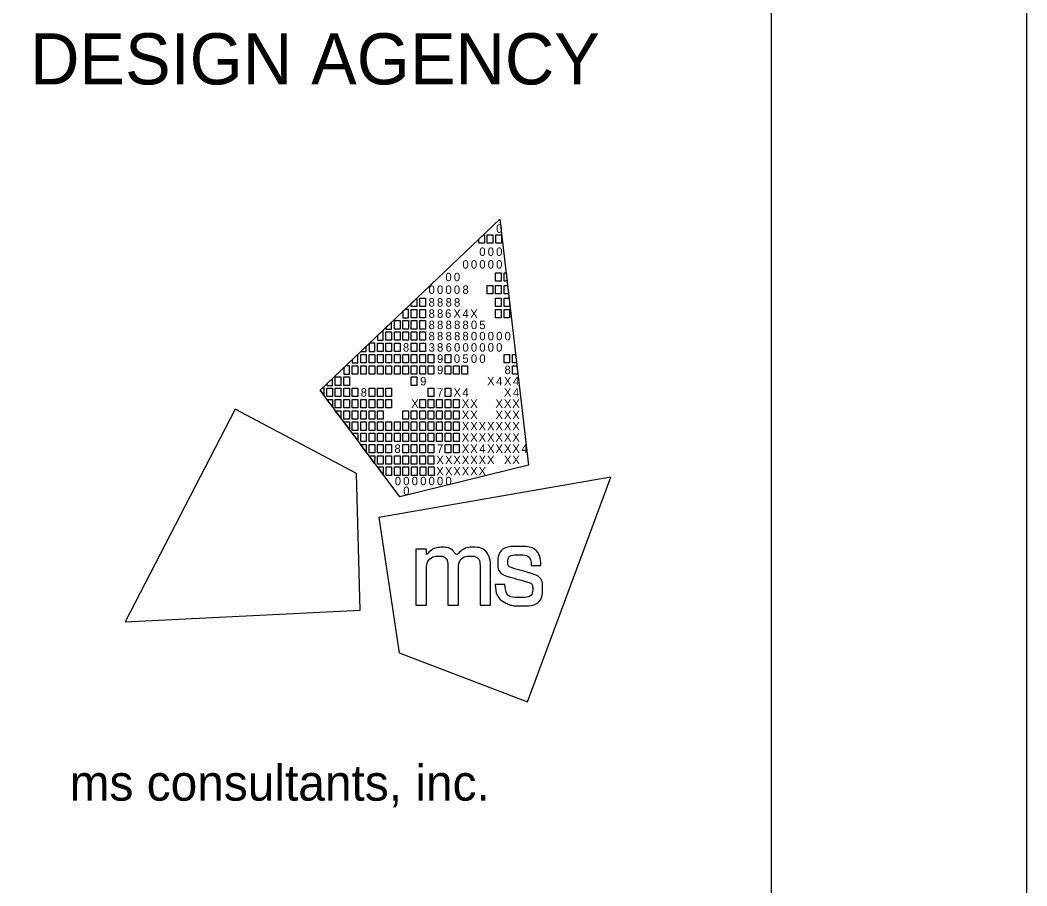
# Model space of a CAD drawing. Extents: x -1.2 to 34, y 0 to 22.
# Drawn here: x 32.03 to 34, y 2.782 to 4.476 of the extents above; entities that cross this region are included whole.
import ezdxf

# ---------------------------------------------------------------- set-up
doc = ezdxf.new("R2010")
doc.units = 0
for name, color, linetype in [('SH_Border', 7, 'Continuous'), ('SH_Cut_Line', 7, 'Continuous'), ('SH_Data', 7, 'Continuous')]:
    doc.layers.add(name, color=color, linetype=linetype)

msp = doc.modelspace()

# ---------------------------------------------------------------- linework, layer by layer
at = {"layer": 'SH_Border'}
for p, q in [((32.6175, 3.7519), (32.9688, 4.0861)), ((32.9688, 4.0861), (32.9688, 4.0861)), ((32.9688, 4.0861), (33.0253, 3.6052)), ((32.773, 3.543), (32.6175, 3.7519)), ((33.0253, 3.6052), (32.773, 3.543))]:
    msp.add_line(p, q, dxfattribs=at)
for points in [[(1.5, 21.5), (33.5, 21.5), (33.5, 0.5), (1.5, 0.5)], [(32.9279, 4.0472), (32.9369, 4.0558), (32.9389, 4.0558), (32.9389, 4.0393), (32.9279, 4.0393)], [(32.9444, 4.0558), (32.9554, 4.0558), (32.9554, 4.0393), (32.9444, 4.0393)], [(32.9609, 4.0558), (32.9719, 4.0558), (32.9719, 4.0393), (32.9609, 4.0393)], [(32.9606, 3.9815), (32.9716, 3.9815), (32.9716, 3.965), (32.9606, 3.965)], [(32.9771, 3.9815), (32.9811, 3.9815), (32.983, 3.965), (32.9771, 3.965)], [(32.9441, 3.9567), (32.9551, 3.9567), (32.9551, 3.9402), (32.9441, 3.9402)], [(32.9606, 3.9567), (32.9716, 3.9567), (32.9716, 3.9402), (32.9606, 3.9402)], [(32.9771, 3.9567), (32.984, 3.9567), (32.9859, 3.9402), (32.9771, 3.9402)], [(32.7953, 3.9211), (32.8064, 3.9316), (32.8064, 3.9154), (32.7953, 3.9154)], [(32.8123, 3.9319), (32.8233, 3.9319), (32.8233, 3.9154), (32.8123, 3.9154)], [(32.9606, 3.9319), (32.9716, 3.9319), (32.9716, 3.9154), (32.9606, 3.9154)], [(32.9771, 3.9319), (32.9869, 3.9319), (32.9881, 3.9218), (32.9881, 3.9154), (32.9771, 3.9154)], [(32.7958, 3.9099), (32.8068, 3.9099), (32.8068, 3.8934), (32.7958, 3.8934)], [(32.8123, 3.9099), (32.8233, 3.9099), (32.8233, 3.8934), (32.8123, 3.8934)], [(32.9606, 3.9099), (32.9716, 3.9099), (32.9716, 3.8934), (32.9606, 3.8934)], [(32.9771, 3.9099), (32.9881, 3.9099), (32.9881, 3.8934), (32.9771, 3.8934)], [(32.7627, 3.8879), (32.7737, 3.8879), (32.7737, 3.8714), (32.7627, 3.8714)], [(32.7793, 3.8879), (32.7903, 3.8879), (32.7903, 3.8714), (32.7793, 3.8714)], [(32.7958, 3.8879), (32.8068, 3.8879), (32.8068, 3.8714), (32.7958, 3.8714)], [(32.8123, 3.8879), (32.8233, 3.8879), (32.8233, 3.8714), (32.8123, 3.8714)], [(32.7462, 3.8659), (32.7572, 3.8659), (32.7572, 3.8494), (32.7462, 3.8494)], [(32.7627, 3.8659), (32.7737, 3.8659), (32.7737, 3.8494), (32.7627, 3.8494)], [(32.7793, 3.8659), (32.7903, 3.8659), (32.7903, 3.8494), (32.7793, 3.8494)], [(32.7958, 3.8659), (32.8068, 3.8659), (32.8068, 3.8494), (32.7958, 3.8494)], [(32.8123, 3.8659), (32.8233, 3.8659), (32.8233, 3.8494), (32.8123, 3.8494)], [(32.7297, 3.8439), (32.7407, 3.8439), (32.7407, 3.8273), (32.7297, 3.8273)], [(32.7462, 3.8439), (32.7572, 3.8439), (32.7572, 3.8273), (32.7462, 3.8273)], [(32.7627, 3.8439), (32.7737, 3.8439), (32.7737, 3.8273), (32.7627, 3.8273)], [(32.7958, 3.8439), (32.8068, 3.8439), (32.8068, 3.8273), (32.7958, 3.8273)], [(32.8123, 3.8439), (32.8233, 3.8439), (32.8233, 3.8273), (32.8123, 3.8273)], [(32.6967, 3.8218), (32.7077, 3.8218), (32.7077, 3.8053), (32.6967, 3.8053)], [(32.7132, 3.8218), (32.7242, 3.8218), (32.7242, 3.8053), (32.7132, 3.8053)], [(32.7297, 3.8218), (32.7407, 3.8218), (32.7407, 3.8053), (32.7297, 3.8053)], [(32.7462, 3.8218), (32.7572, 3.8218), (32.7572, 3.8053), (32.7462, 3.8053)], [(32.7627, 3.8218), (32.7737, 3.8218), (32.7737, 3.8053), (32.7627, 3.8053)], [(32.7793, 3.8218), (32.7903, 3.8218), (32.7903, 3.8053), (32.7793, 3.8053)], [(32.7958, 3.8218), (32.8068, 3.8218), (32.8068, 3.8053), (32.7958, 3.8053)], [(32.8123, 3.8218), (32.8233, 3.8218), (32.8233, 3.8053), (32.8123, 3.8053)], [(32.8288, 3.8218), (32.8398, 3.8218), (32.8398, 3.8053), (32.8288, 3.8053)], [(32.8618, 3.8218), (32.8728, 3.8218), (32.8728, 3.8053), (32.8618, 3.8053)], [(32.9771, 3.8218), (32.9881, 3.8218), (32.9881, 3.8053), (32.9771, 3.8053)], [(32.9935, 3.8218), (32.9998, 3.8218), (33.0018, 3.8053), (32.9935, 3.8053)], [(32.6802, 3.7998), (32.6912, 3.7998), (32.6912, 3.7833), (32.6802, 3.7833)], [(32.6967, 3.7998), (32.7077, 3.7998), (32.7077, 3.7833), (32.6967, 3.7833)], [(32.7132, 3.7998), (32.7242, 3.7998), (32.7242, 3.7833), (32.7132, 3.7833)], [(32.7297, 3.7998), (32.7407, 3.7998), (32.7407, 3.7833), (32.7297, 3.7833)], [(32.7462, 3.7998), (32.7572, 3.7998), (32.7572, 3.7833), (32.7462, 3.7833)], [(32.7627, 3.7998), (32.7737, 3.7998), (32.7737, 3.7833), (32.7627, 3.7833)], [(32.7793, 3.7998), (32.7903, 3.7998), (32.7903, 3.7833), (32.7793, 3.7833)], [(32.7958, 3.7998), (32.8068, 3.7998), (32.8068, 3.7833), (32.7958, 3.7833)], [(32.8123, 3.7998), (32.8233, 3.7998), (32.8233, 3.7833), (32.8123, 3.7833)], [(32.8288, 3.7998), (32.8398, 3.7998), (32.8398, 3.7833), (32.8288, 3.7833)], [(32.8618, 3.7998), (32.8728, 3.7998), (32.8728, 3.7833), (32.8618, 3.7833)], [(32.8783, 3.7998), (32.8893, 3.7998), (32.8893, 3.7833), (32.8783, 3.7833)], [(32.8947, 3.7998), (32.9057, 3.7998), (32.9057, 3.7833), (32.8947, 3.7833)], [(32.9935, 3.7998), (33.0024, 3.7998), (33.0044, 3.7833), (32.9935, 3.7833)], [(32.6471, 3.7778), (32.6581, 3.7778), (32.6581, 3.7613), (32.6471, 3.7613)], [(32.6637, 3.7778), (32.6747, 3.7778), (32.6747, 3.7613), (32.6637, 3.7613)], [(32.7958, 3.7778), (32.8068, 3.7778), (32.8068, 3.7613), (32.7958, 3.7613)], [(32.6306, 3.7558), (32.6416, 3.7558), (32.6416, 3.7393), (32.6306, 3.7393)], [(32.6471, 3.7558), (32.6581, 3.7558), (32.6581, 3.7393), (32.6471, 3.7393)], [(32.6637, 3.7558), (32.6747, 3.7558), (32.6747, 3.7393), (32.6637, 3.7393)], [(32.6802, 3.7558), (32.6912, 3.7558), (32.6912, 3.7393), (32.6802, 3.7393)], [(32.7132, 3.7558), (32.7242, 3.7558), (32.7242, 3.7393), (32.7132, 3.7393)], [(32.7297, 3.7558), (32.7407, 3.7558), (32.7407, 3.7393), (32.7297, 3.7393)], [(32.7462, 3.7558), (32.7572, 3.7558), (32.7572, 3.7393), (32.7462, 3.7393)], [(32.8288, 3.7558), (32.8398, 3.7558), (32.8398, 3.7393), (32.8288, 3.7393)], [(32.8618, 3.7558), (32.8728, 3.7558), (32.8728, 3.7393), (32.8618, 3.7393)], [(32.6306, 3.7338), (32.6416, 3.7338), (32.6416, 3.72)], [(32.6471, 3.7338), (32.6581, 3.7338), (32.6581, 3.7173), (32.6471, 3.7173)], [(32.6637, 3.7338), (32.6747, 3.7338), (32.6747, 3.7173), (32.6637, 3.7173)], [(32.6802, 3.7338), (32.6912, 3.7338), (32.6912, 3.7173), (32.6802, 3.7173)], [(32.6967, 3.7338), (32.7077, 3.7338), (32.7077, 3.7173), (32.6967, 3.7173)], [(32.7132, 3.7338), (32.7242, 3.7338), (32.7242, 3.7173), (32.7132, 3.7173)], [(32.7297, 3.7338), (32.7407, 3.7338), (32.7407, 3.7173), (32.7297, 3.7173)], [(32.7462, 3.7338), (32.7572, 3.7338), (32.7572, 3.7173), (32.7462, 3.7173)], [(32.8123, 3.7338), (32.8233, 3.7338), (32.8233, 3.7173), (32.8123, 3.7173)], [(32.8288, 3.7338), (32.8398, 3.7338), (32.8398, 3.7173), (32.8288, 3.7173)], [(32.8453, 3.7338), (32.8563, 3.7338), (32.8563, 3.7173), (32.8453, 3.7173)], [(32.8618, 3.7338), (32.8728, 3.7338), (32.8728, 3.7173), (32.8618, 3.7173)], [(32.8783, 3.7338), (32.8893, 3.7338), (32.8893, 3.7173), (32.8783, 3.7173)], [(32.6471, 3.7117), (32.6581, 3.7117), (32.6581, 3.698)], [(32.6637, 3.7117), (32.6747, 3.7117), (32.6747, 3.6952), (32.6637, 3.6952)], [(32.6802, 3.7117), (32.6912, 3.7117), (32.6912, 3.6952), (32.6802, 3.6952)], [(32.6967, 3.7117), (32.7077, 3.7117), (32.7077, 3.6952), (32.6967, 3.6952)], [(32.7132, 3.7117), (32.7242, 3.7117), (32.7242, 3.6952), (32.7132, 3.6952)], [(32.7297, 3.7117), (32.7407, 3.7117), (32.7407, 3.6952), (32.7297, 3.6952)], [(32.7793, 3.7117), (32.7903, 3.7117), (32.7903, 3.6952), (32.7793, 3.6952)], [(32.7958, 3.7117), (32.8068, 3.7117), (32.8068, 3.6952), (32.7958, 3.6952)], [(32.8123, 3.7117), (32.8233, 3.7117), (32.8233, 3.6952), (32.8123, 3.6952)], [(32.8288, 3.7117), (32.8398, 3.7117), (32.8398, 3.6952), (32.8288, 3.6952)], [(32.8453, 3.7117), (32.8563, 3.7117), (32.8563, 3.6952), (32.8453, 3.6952)], [(32.8618, 3.7117), (32.8728, 3.7117), (32.8728, 3.6952), (32.8618, 3.6952)], [(32.8783, 3.7117), (32.8893, 3.7117), (32.8893, 3.6952), (32.8783, 3.6952)], [(32.6637, 3.6897), (32.6747, 3.6897), (32.6747, 3.676)], [(32.6747, 3.6897), (32.6747, 3.6897), (32.6747, 3.6897)], [(32.6802, 3.6897), (32.6912, 3.6897), (32.6912, 3.6732), (32.6802, 3.6732)], [(32.6967, 3.6897), (32.7077, 3.6897), (32.7077, 3.6732), (32.6967, 3.6732)], [(32.7132, 3.6897), (32.7242, 3.6897), (32.7242, 3.6732), (32.7132, 3.6732)], [(32.7297, 3.6897), (32.7407, 3.6897), (32.7407, 3.6732), (32.7297, 3.6732)], [(32.7462, 3.6897), (32.7572, 3.6897), (32.7572, 3.6732), (32.7462, 3.6732)], [(32.7627, 3.6897), (32.7737, 3.6897), (32.7737, 3.6732), (32.7627, 3.6732)], [(32.7793, 3.6897), (32.7903, 3.6897), (32.7903, 3.6732), (32.7793, 3.6732)], [(32.7958, 3.6897), (32.8068, 3.6897), (32.8068, 3.6732), (32.7958, 3.6732)], [(32.8123, 3.6897), (32.8233, 3.6897), (32.8233, 3.6732), (32.8123, 3.6732)], [(32.8288, 3.6897), (32.8398, 3.6897), (32.8398, 3.6732), (32.8288, 3.6732)], [(32.8453, 3.6897), (32.8563, 3.6897), (32.8563, 3.6732), (32.8453, 3.6732)], [(32.8618, 3.6897), (32.8728, 3.6897), (32.8728, 3.6732), (32.8618, 3.6732)], [(32.8783, 3.6897), (32.8893, 3.6897), (32.8893, 3.6732), (32.8783, 3.6732)], [(32.6802, 3.6677), (32.6912, 3.6677), (32.6912, 3.654)], [(32.6967, 3.6677), (32.7077, 3.6677), (32.7077, 3.6512), (32.6967, 3.6512)], [(32.7132, 3.6677), (32.7242, 3.6677), (32.7242, 3.6512), (32.7132, 3.6512)], [(32.7297, 3.6677), (32.7407, 3.6677), (32.7407, 3.6512), (32.7297, 3.6512)], [(32.7462, 3.6677), (32.7572, 3.6677), (32.7572, 3.6512), (32.7462, 3.6512)], [(32.7627, 3.6677), (32.7737, 3.6677), (32.7737, 3.6512), (32.7627, 3.6512)], [(32.7793, 3.6677), (32.7903, 3.6677), (32.7903, 3.6512), (32.7793, 3.6512)], [(32.7958, 3.6677), (32.8068, 3.6677), (32.8068, 3.6512), (32.7958, 3.6512)], [(32.8123, 3.6677), (32.8233, 3.6677), (32.8233, 3.6512), (32.8123, 3.6512)], [(32.8288, 3.6677), (32.8398, 3.6677), (32.8398, 3.6512), (32.8288, 3.6512)], [(32.8453, 3.6677), (32.8563, 3.6677), (32.8563, 3.6512), (32.8453, 3.6512)], [(32.8618, 3.6677), (32.8728, 3.6677), (32.8728, 3.6512), (32.8618, 3.6512)], [(32.8783, 3.6677), (32.8893, 3.6677), (32.8893, 3.6512), (32.8783, 3.6512)], [(32.7077, 3.6305), (32.6965, 3.6457), (32.7077, 3.6457)], [(32.7132, 3.6457), (32.7242, 3.6457), (32.7242, 3.6292), (32.7132, 3.6292)], [(32.7297, 3.6457), (32.7407, 3.6457), (32.7407, 3.6292), (32.7297, 3.6292)], [(32.7462, 3.6457), (32.7572, 3.6457), (32.7572, 3.6292), (32.7462, 3.6292)], [(32.7793, 3.6457), (32.7903, 3.6457), (32.7903, 3.6292), (32.7793, 3.6292)], [(32.7958, 3.6457), (32.8068, 3.6457), (32.8068, 3.6292), (32.7958, 3.6292)], [(32.8123, 3.6457), (32.8233, 3.6457), (32.8233, 3.6292), (32.8123, 3.6292)], [(32.8288, 3.6457), (32.8398, 3.6457), (32.8398, 3.6292), (32.8288, 3.6292)], [(32.8618, 3.6457), (32.8728, 3.6457), (32.8728, 3.6292), (32.8618, 3.6292)], [(32.8783, 3.6457), (32.8893, 3.6457), (32.8893, 3.6292), (32.8783, 3.6292)], [(32.724, 3.6082), (32.7132, 3.6237), (32.7242, 3.6237)], [(32.7297, 3.6237), (32.7407, 3.6237), (32.7407, 3.6072), (32.7297, 3.6072)], [(32.7462, 3.6237), (32.7572, 3.6237), (32.7572, 3.6072), (32.7462, 3.6072)], [(32.7627, 3.6237), (32.7737, 3.6237), (32.7737, 3.6072), (32.7627, 3.6072)], [(32.7793, 3.6237), (32.7903, 3.6237), (32.7903, 3.6072), (32.7793, 3.6072)], [(32.7958, 3.6237), (32.8068, 3.6237), (32.8068, 3.6072), (32.7958, 3.6072)], [(32.8123, 3.6237), (32.8233, 3.6237), (32.8233, 3.6072), (32.8123, 3.6072)], [(32.8288, 3.6237), (32.8398, 3.6237), (32.8398, 3.6072), (32.8288, 3.6072)], [(32.7302, 3.6017), (32.7407, 3.6017), (32.7408, 3.5875)], [(32.7463, 3.6017), (32.7573, 3.6017), (32.7573, 3.5852), (32.7463, 3.5852)], [(32.763, 3.6017), (32.774, 3.6017), (32.774, 3.5852), (32.763, 3.5852)], [(32.7794, 3.6017), (32.7904, 3.6017), (32.7904, 3.5852), (32.7794, 3.5852)], [(32.796, 3.6017), (32.807, 3.6017), (32.807, 3.5852), (32.796, 3.5852)], [(32.8129, 3.6017), (32.8239, 3.6017), (32.8239, 3.5851), (32.8129, 3.5851)], [(32.8296, 3.6017), (32.8406, 3.6017), (32.8406, 3.5851), (32.8296, 3.5851)]]:
    msp.add_lwpolyline(points, close=True, dxfattribs=at)
for points in [[(32.7903, 3.9099), (32.7836, 3.9099), (32.7793, 3.9058), (32.7793, 3.8934), (32.7903, 3.8934), (32.7903, 3.9099)], [(32.7572, 3.8849), (32.7462, 3.8744), (32.7462, 3.8714), (32.7572, 3.8714), (32.7572, 3.8849)], [(32.7407, 3.8691), (32.7297, 3.8587), (32.7297, 3.8494), (32.7407, 3.8494), (32.7407, 3.8691)], [(32.7242, 3.8439), (32.7141, 3.8439), (32.7132, 3.843), (32.7132, 3.8273), (32.7242, 3.8273), (32.7242, 3.8439)], [(32.6912, 3.822), (32.6802, 3.8115), (32.6802, 3.8053), (32.6912, 3.8053), (32.6912, 3.822)], [(32.7077, 3.8377), (32.6968, 3.8273), (32.7077, 3.8273), (32.7077, 3.8377)], [(32.6747, 3.7998), (32.6679, 3.7998), (32.6637, 3.7958), (32.6637, 3.7833), (32.6747, 3.7833), (32.6747, 3.7998)], [(32.6416, 3.7749), (32.6306, 3.7644), (32.6306, 3.7613), (32.6416, 3.7613), (32.6416, 3.7749)], [(32.6251, 3.7558), (32.6216, 3.7558), (32.6175, 3.7519), (32.6251, 3.7417), (32.6251, 3.7558)], [(32.4512, 3.7149), (32.2359, 3.2988), (32.6956, 3.3215), (32.6884, 3.5892), (32.4512, 3.7149)], [(33.0229, 3.1422), (33.1859, 3.5814), (32.7324, 3.5029), (32.7722, 3.2381), (33.0229, 3.1422)]]:
    msp.add_lwpolyline(points, dxfattribs=at)
for points in [[(32.8048, 3.3315), (32.8048, 3.3315), (32.8048, 3.4409), (32.8048, 3.4409), (32.8048, 3.4409), (32.8255, 3.4409), (32.8255, 3.4409), (32.8255, 3.4409), (32.8255, 3.4297), (32.8255, 3.4297), (32.8346, 3.4399), (32.8457, 3.4445), (32.8555, 3.4445), (32.8688, 3.4445), (32.8791, 3.4372), (32.8837, 3.4266), (32.8915, 3.4381), (32.905, 3.4446), (32.9166, 3.4446), (32.9325, 3.4446), (32.9451, 3.435), (32.9494, 3.4213), (32.9494, 3.4212), (32.9494, 3.4212), (32.9494, 3.4212), (32.9501, 3.419), (32.9506, 3.4172), (32.9506, 3.4071), (32.9506, 3.4071), (32.9506, 3.3314), (32.9506, 3.3314), (32.9506, 3.3314), (32.9303, 3.3314), (32.9303, 3.3314), (32.9303, 3.3314), (32.9303, 3.4048), (32.9303, 3.4048), (32.9303, 3.4201), (32.9219, 3.4274), (32.911, 3.4274), (32.8995, 3.4274), (32.8879, 3.4171), (32.8879, 3.4001), (32.8879, 3.4001), (32.8879, 3.3315), (32.8879, 3.3315), (32.8879, 3.3315), (32.8674, 3.3315), (32.8674, 3.3315), (32.8674, 3.3315), (32.8674, 3.4059), (32.8674, 3.4059), (32.8674, 3.4203), (32.8588, 3.4274), (32.8496, 3.4274), (32.8384, 3.4274), (32.8254, 3.417), (32.8254, 3.3962), (32.8254, 3.3962), (32.8254, 3.3315), (32.8254, 3.3315), (32.8254, 3.3315), (32.8048, 3.3315), (32.8048, 3.3315)], [(32.9595, 3.3709), (32.9595, 3.3709), (32.9595, 3.3717), (32.9595, 3.3717), (32.9595, 3.3717), (32.9603, 3.3717), (32.9603, 3.3717), (32.9603, 3.3717), (32.9783, 3.3717), (32.9783, 3.3717), (32.9783, 3.3717), (32.9789, 3.3717), (32.9789, 3.3717), (32.9789, 3.3717), (32.979, 3.371), (32.979, 3.371), (32.9803, 3.3554), (32.9887, 3.346), (33.009, 3.346), (33.0273, 3.346), (33.0333, 3.3554), (33.0333, 3.3631), (33.0333, 3.3732), (33.0256, 3.3758), (33.0175, 3.378), (33.0175, 3.378), (32.987, 3.3867), (32.987, 3.3867), (32.972, 3.3909), (32.9648, 3.4019), (32.9648, 3.4142), (32.9648, 3.4303), (32.9768, 3.4462), (33.0052, 3.4462), (33.0348, 3.4462), (33.0489, 3.4285), (33.0489, 3.4095), (33.0489, 3.4095), (33.0489, 3.4087), (33.0489, 3.4087), (33.0489, 3.4087), (33.0482, 3.4087), (33.0482, 3.4087), (33.0482, 3.4087), (33.0312, 3.4087), (33.0312, 3.4087), (33.0312, 3.4087), (33.0305, 3.4087), (33.0305, 3.4087), (33.0305, 3.4087), (33.0305, 3.4094), (33.0305, 3.4094), (33.0301, 3.4208), (33.0226, 3.43), (33.0056, 3.43), (32.9891, 3.43), (32.9843, 3.4218), (32.9843, 3.4157), (32.9843, 3.4108), (32.9869, 3.4059), (32.9959, 3.4033), (32.9959, 3.4033), (33.0255, 3.3948), (33.0255, 3.3948), (33.0462, 3.3889), (33.0527, 3.3777), (33.0527, 3.3639), (33.0527, 3.3462), (33.041, 3.3298), (33.0087, 3.3298), (32.9952, 3.3298), (32.9877, 3.3321), (32.9823, 3.3348), (32.969, 3.3414), (32.9609, 3.3536), (32.9595, 3.3709)]]:
    msp.add_open_spline(points, degree=3, dxfattribs=at)
at = {"layer": 'SH_Cut_Line'}
msp.add_lwpolyline([(0, 0), (34, 0), (34, 22), (0, 22)], close=True, dxfattribs=at)
at = {"layer": 'SH_Data'}
msp.add_line((32.75, 3.5), (32.75, 3.5), dxfattribs=at)

# ---------------------------------------------------------------- texts
at = {"layer": 'SH_Border'}
for s, height, p in [('0', 0.0165, (32.9617, 4.0597)), ('0', 0.0165, (32.9288, 4.0145)), ('0', 0.0165, (32.9452, 4.0145)), ('0', 0.0165, (32.9617, 4.0145)), ('0', 0.0165, (32.8958, 3.9897)), ('0', 0.0165, (32.9123, 3.9897)), ('0', 0.0165, (32.9288, 3.9897)), ('0', 0.0165, (32.9452, 3.9897)), ('0', 0.0165, (32.9617, 3.9897)), ('0', 0.0165, (32.8625, 3.965)), ('0', 0.0165, (32.879, 3.965)), ('0', 0.0165, (32.8295, 3.9402)), ('0', 0.0165, (32.846, 3.9402)), ('0', 0.0165, (32.8625, 3.9402)), ('0', 0.0165, (32.879, 3.9402)), ('8', 0.0165, (32.8958, 3.9402)), ('8', 0.0165, (32.8295, 3.9154)), ('8', 0.0165, (32.846, 3.9154)), ('8', 0.0165, (32.8628, 3.9154)), ('8', 0.0165, (32.8793, 3.9154)), ('8', 0.0165, (32.8295, 3.8934)), ('8', 0.0165, (32.846, 3.8934)), ('6', 0.0165, (32.8618, 3.8934)), ('X', 0.0165, (32.8781, 3.8934)), ('4', 0.0165, (32.8958, 3.8934)), ('X', 0.0165, (32.911, 3.8934)), ('8', 0.0165, (32.8295, 3.8713)), ('8', 0.0165, (32.846, 3.8713)), ('8', 0.0165, (32.8628, 3.8713)), ('8', 0.0165, (32.8794, 3.8713)), ('8', 0.0165, (32.8958, 3.8713)), ('0', 0.0165, (32.9123, 3.8713)), ('5', 0.0165, (32.9287, 3.8713)), ('8', 0.0165, (32.8295, 3.8494)), ('8', 0.0165, (32.846, 3.8494)), ('8', 0.0165, (32.8628, 3.8494)), ('8', 0.0165, (32.8794, 3.8494)), ('8', 0.0165, (32.8958, 3.8494)), ('0', 0.0165, (32.9123, 3.8494)), ('0', 0.0165, (32.9288, 3.8494)), ('0', 0.0165, (32.9452, 3.8494)), ('0', 0.0165, (32.9617, 3.8494)), ('0', 0.0165, (32.9782, 3.8494)), ('8', 0.0165, (32.7793, 3.8273)), ('3', 0.0165, (32.8295, 3.8273)), ('8', 0.0165, (32.846, 3.8273)), ('6', 0.0165, (32.8629, 3.8273)), ('0', 0.0165, (32.8793, 3.8273)), ('0', 0.0165, (32.8958, 3.8273)), ('0', 0.0165, (32.9123, 3.8273)), ('0', 0.0165, (32.9288, 3.8273)), ('0', 0.0165, (32.9452, 3.8273)), ('0', 0.0165, (32.9617, 3.8273)), ('9', 0.0165, (32.846, 3.8053)), ('0', 0.0165, (32.879, 3.8053)), ('5', 0.0165, (32.8957, 3.8053)), ('0', 0.0165, (32.9123, 3.8053)), ('0', 0.0165, (32.9288, 3.8053)), ('9', 0.0165, (32.846, 3.7833)), ('8', 0.0165, (32.9781, 3.7833)), ('9', 0.0165, (32.813, 3.7613)), ('X', 0.0165, (32.9439, 3.7613)), ('4', 0.0165, (32.9617, 3.7613)), ('X', 0.0165, (32.9769, 3.7613)), ('4', 0.0165, (32.9946, 3.7613)), ('8', 0.0165, (32.6967, 3.7393)), ('7', 0.0165, (32.846, 3.7393)), ('X', 0.0165, (32.8781, 3.7393)), ('4', 0.0165, (32.8958, 3.7393)), ('X', 0.0165, (32.9769, 3.7393)), ('4', 0.0165, (32.9946, 3.7393)), ('X', 0.0165, (32.7955, 3.7173)), ('X', 0.0165, (32.8945, 3.7173)), ('X', 0.0165, (32.911, 3.7173)), ('X', 0.0165, (32.9604, 3.7173)), ('X', 0.0165, (32.9769, 3.7173)), ('X', 0.0165, (32.9933, 3.7173)), ('X', 0.0165, (32.8945, 3.6952)), ('X', 0.0165, (32.911, 3.6952)), ('X', 0.0165, (32.9604, 3.6952)), ('X', 0.0165, (32.9769, 3.6952)), ('X', 0.0165, (32.9933, 3.6952)), ('X', 0.0165, (32.8945, 3.6732)), ('X', 0.0165, (32.911, 3.6732)), ('X', 0.0165, (32.9274, 3.6732)), ('X', 0.0165, (32.9439, 3.6732)), ('X', 0.0165, (32.9604, 3.6732)), ('X', 0.0165, (32.9769, 3.6732)), ('X', 0.0165, (32.9933, 3.6732)), ('X', 0.0165, (32.8945, 3.6512)), ('X', 0.0165, (32.911, 3.6512)), ('X', 0.0165, (32.9274, 3.6512)), ('X', 0.0165, (32.9439, 3.6512)), ('X', 0.0165, (32.9604, 3.6512)), ('X', 0.0165, (32.9769, 3.6512)), ('X', 0.0165, (32.9933, 3.6512)), ('8', 0.0165, (32.7627, 3.6292)), ('7', 0.0165, (32.846, 3.6292)), ('X', 0.0165, (32.8945, 3.6292)), ('X', 0.0165, (32.911, 3.6292)), ('4', 0.0165, (32.9288, 3.6292)), ('X', 0.0165, (32.9439, 3.6292)), ('X', 0.0165, (32.9604, 3.6292)), ('X', 0.0165, (32.9769, 3.6292)), ('X', 0.0165, (32.9933, 3.6292)), ('4', 0.0165, (33.0111, 3.6292)), ('X', 0.0165, (32.8447, 3.6072)), ('X', 0.0165, (32.8616, 3.6072)), ('X', 0.0165, (32.878, 3.6072)), ('X', 0.0165, (32.8945, 3.6072)), ('X', 0.0165, (32.911, 3.6072)), ('X', 0.0165, (32.9274, 3.6072)), ('X', 0.0165, (32.9439, 3.6072)), ('X', 0.0165, (32.9771, 3.6072)), ('X', 0.0165, (32.9933, 3.6072)), ('X', 0.0165, (32.8447, 3.5851)), ('X', 0.0165, (32.8616, 3.5851)), ('X', 0.0165, (32.878, 3.5851)), ('X', 0.0165, (32.8945, 3.5851)), ('X', 0.0165, (32.911, 3.5851)), ('X', 0.0165, (32.9274, 3.5851)), ('0', 0.0165, (32.7634, 3.5659)), ('0', 0.0165, (32.7799, 3.5659)), ('0', 0.0165, (32.7965, 3.5659)), ('0', 0.0165, (32.813, 3.5659)), ('0', 0.0165, (32.8295, 3.5659)), ('0', 0.0165, (32.846, 3.5659)), ('0', 0.0165, (32.8625, 3.5659)), ('0', 0.0165, (32.7799, 3.5467)), ('ms consultants, inc.', 0.07, (32.1273, 2.9489))]:
    msp.add_text(s, height=height, rotation=360, dxfattribs=at).set_placement(p)
at = {"layer": 'SH_Data'}
msp.add_text('DESIGN AGENCY', height=0.1, dxfattribs=at).set_placement((32.05, 4.35))

doc.saveas('drawing.dxf')
